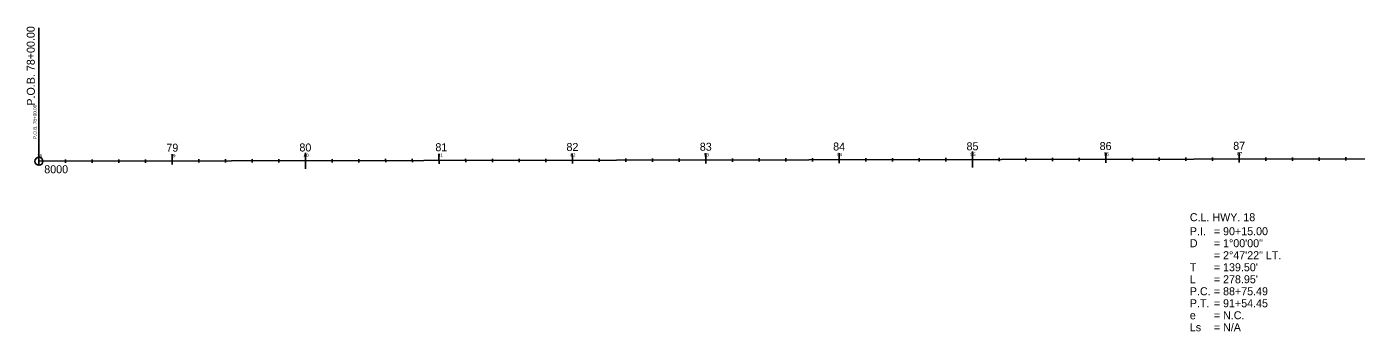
# Model space of a CAD drawing. Extents: x 1708585 to 1714116, y 541444 to 545437.
# Drawn here: x 1709801 to 1710798, y 544124 to 544352 of the extents above; entities that cross this region are included whole.
import ezdxf

# ---------------------------------------------------------------- set-up
doc = ezdxf.new("R2010")
doc.units = 0
for name, color, linetype in [('CL_Highway_1', 7, 'Continuous'), ('CL_Highway_1_40_PText', 7, 'Continuous'), ('CL_Highway_1_40_Sta', 7, 'Continuous'), ('CL_Highway_1_PText', 7, 'Continuous'), ('CL_Highway_1_Sta', 7, 'Continuous'), ('CL_Highway_1_Sta_Minor_Text', 7, 'Continuous'), ('CurveData_100', 7, 'Continuous'), ('Point_CL_Highway_1', 7, 'Continuous'), ('Point_Number', 7, 'Continuous')]:
    doc.layers.add(name, color=color, linetype=linetype)

msp = doc.modelspace()

# ---------------------------------------------------------------- linework, layer by layer
at = {"layer": 'CL_Highway_1'}
msp.add_line((1709809.9, 544251.39), (1710885.4, 544253.27), dxfattribs=at)
at = {"layer": 'CL_Highway_1_40_PText'}
msp.add_lwpolyline([(1709809.9, 544251.39), (1709809.83, 544291.39)], dxfattribs=at)
at = {"layer": 'CL_Highway_1_40_Sta'}
for points in [[(1709809.9, 544253.89), (1709809.91, 544248.89)], [(1709829.9, 544252.68), (1709829.91, 544250.18)], [(1709849.9, 544252.71), (1709849.91, 544250.21)], [(1709869.9, 544252.75), (1709869.91, 544250.25)], [(1709889.9, 544252.78), (1709889.91, 544250.28)], [(1709909.9, 544254.07), (1709909.91, 544249.07)], [(1709929.9, 544252.85), (1709929.91, 544250.35)], [(1709949.9, 544252.89), (1709949.91, 544250.39)], [(1709969.9, 544252.92), (1709969.91, 544250.42)], [(1709989.9, 544252.96), (1709989.91, 544250.46)], [(1710009.9, 544254.24), (1710009.91, 544249.24)], [(1710029.9, 544253.03), (1710029.91, 544250.53)], [(1710049.9, 544253.06), (1710049.91, 544250.56)], [(1710069.9, 544253.1), (1710069.91, 544250.6)], [(1710089.9, 544253.13), (1710089.91, 544250.63)], [(1710109.9, 544254.42), (1710109.91, 544249.42)], [(1710129.9, 544253.2), (1710129.91, 544250.7)], [(1710149.9, 544253.24), (1710149.91, 544250.74)], [(1710169.9, 544253.27), (1710169.91, 544250.77)], [(1710189.9, 544253.31), (1710189.91, 544250.81)], [(1710209.9, 544254.59), (1710209.91, 544249.59)], [(1710229.9, 544253.38), (1710229.91, 544250.88)], [(1710249.9, 544253.41), (1710249.91, 544250.91)], [(1710269.9, 544253.45), (1710269.91, 544250.95)], [(1710289.9, 544253.48), (1710289.91, 544250.98)], [(1710309.9, 544254.77), (1710309.91, 544249.77)], [(1710329.9, 544253.55), (1710329.9, 544251.05)], [(1710349.9, 544253.59), (1710349.9, 544251.09)], [(1710369.9, 544253.62), (1710369.9, 544251.12)], [(1710389.9, 544253.66), (1710389.9, 544251.16)], [(1710409.9, 544254.94), (1710409.91, 544249.94)], [(1710429.9, 544253.73), (1710429.9, 544251.23)], [(1710449.9, 544253.76), (1710449.9, 544251.26)], [(1710469.9, 544253.8), (1710469.9, 544251.3)], [(1710489.9, 544253.83), (1710489.9, 544251.33)], [(1710509.9, 544255.11), (1710509.91, 544250.11)], [(1710529.9, 544253.9), (1710529.9, 544251.4)], [(1710549.9, 544253.93), (1710549.9, 544251.43)], [(1710569.9, 544253.97), (1710569.9, 544251.47)], [(1710589.9, 544254), (1710589.9, 544251.5)], [(1710609.9, 544255.29), (1710609.91, 544250.29)], [(1710629.9, 544254.07), (1710629.9, 544251.57)], [(1710649.9, 544254.11), (1710649.9, 544251.61)], [(1710669.9, 544254.14), (1710669.9, 544251.64)], [(1710689.9, 544254.18), (1710689.9, 544251.68)], [(1710709.9, 544255.46), (1710709.91, 544250.46)], [(1710729.9, 544254.25), (1710729.9, 544251.75)], [(1710749.9, 544254.28), (1710749.9, 544251.78)], [(1710769.9, 544254.32), (1710769.9, 544251.82)], [(1710789.9, 544254.35), (1710789.9, 544251.85)]]:
    msp.add_lwpolyline(points, dxfattribs=at)
at = {"layer": 'CL_Highway_1_PText'}
msp.add_lwpolyline([(1709809.9, 544251.39), (1709809.73, 544351.39)], dxfattribs=at)
at = {"layer": 'CL_Highway_1_Sta'}
for points in [[(1709909.89, 544256.57), (1709909.9, 544251.57)], [(1710009.89, 544257.74), (1710009.91, 544245.74)], [(1710109.89, 544256.92), (1710109.9, 544251.92)], [(1710209.89, 544257.09), (1710209.9, 544252.09)], [(1710309.89, 544257.27), (1710309.9, 544252.27)], [(1710409.89, 544257.44), (1710409.9, 544252.44)], [(1710509.89, 544258.61), (1710509.91, 544246.61)], [(1710609.89, 544257.79), (1710609.9, 544252.79)], [(1710709.89, 544257.96), (1710709.9, 544252.96)]]:
    msp.add_lwpolyline(points, dxfattribs=at)
at = {"layer": 'Point_CL_Highway_1'}
msp.add_circle((1709809.9, 544251.39), 3, dxfattribs=at)

# ---------------------------------------------------------------- texts
at = {"layer": 'CL_Highway_1_40_PText'}
msp.add_text('P.O.B. 78+00.00', height=2.5, rotation=90.10015, dxfattribs=at).set_placement((1709808.12, 544268.07))
at = {"layer": 'CL_Highway_1_40_Sta'}
for s, p in [('78', (1709808.43, 544254.14)), ('79', (1709908.43, 544254.31)), ('80', (1710008.35, 544254.49)), ('81', (1710109, 544254.66)), ('82', (1710208.43, 544254.84)), ('83', (1710308.43, 544255.01)), ('84', (1710408.43, 544255.19)), ('85', (1710508.43, 544255.36)), ('86', (1710608.38, 544255.54)), ('87', (1710708.43, 544255.71))]:
    msp.add_text(s, height=2.5, rotation=0.10015, dxfattribs=at).set_placement(p)
at = {"layer": 'CL_Highway_1_PText'}
msp.add_text('P.O.B. 78+00.00', height=6, rotation=90.10015, dxfattribs=at).set_placement((1709806.83, 544293.08))
at = {"layer": 'CL_Highway_1_Sta'}
for s, p in [('80', (1710005.24, 544258.73)), ('85', (1710505.5, 544259.61))]:
    msp.add_text(s, height=6, rotation=0.10015, dxfattribs=at).set_placement(p)
at = {"layer": 'CL_Highway_1_Sta_Minor_Text'}
for s, p in [('79', (1709905.47, 544258.56)), ('81', (1710107.2, 544258.91)), ('82', (1710205.5, 544259.08)), ('83', (1710305.5, 544259.26)), ('84', (1710405.5, 544259.43)), ('86', (1710605.33, 544259.78)), ('87', (1710705.5, 544259.96))]:
    msp.add_text(s, height=6, rotation=0.10015, dxfattribs=at).set_placement(p)
at = {"layer": 'CurveData_100'}
for s, p in [('C.L. HWY. 18', (1710672.96, 544206.45)), ('P.I.', (1710672.96, 544195.95)), ('= 90+15.00', (1710690.96, 544195.95)), ('D', (1710672.96, 544186.95)), ('= 1%%d00\'00"', (1710690.96, 544186.95)), ('= 2%%d47\'22" LT.', (1710690.96, 544177.95)), ('T', (1710672.96, 544168.95)), ("= 139.50'", (1710690.96, 544168.95)), ('L', (1710672.96, 544159.95)), ("= 278.95'", (1710690.96, 544159.95)), ('P.C.', (1710672.96, 544150.95)), ('= 88+75.49', (1710690.96, 544150.95)), ('P.T.', (1710672.96, 544141.95)), ('= 91+54.45', (1710690.96, 544141.95)), ('e', (1710672.96, 544132.95)), ('= N.C.', (1710690.96, 544132.95)), ('Ls', (1710672.96, 544123.95)), ('= N/A', (1710690.96, 544123.95))]:
    msp.add_text(s, height=6, dxfattribs=at).set_placement(p)
at = {"layer": 'Point_Number'}
msp.add_text('8000', height=6, dxfattribs=at).set_placement((1709813.9, 544242.39))

doc.saveas('drawing.dxf')
